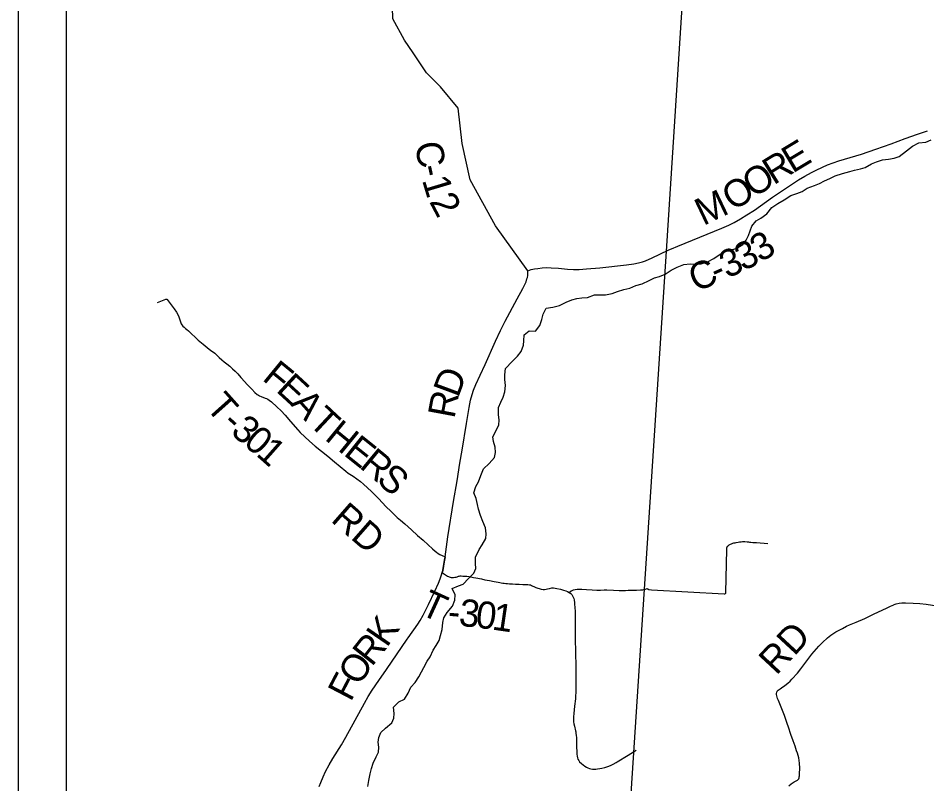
# Model space of a CAD drawing. Extents: x 0 to 34, y 0 to 22.
# Drawn here: x 1.876 to 3.772, y 15.584 to 17.181 of the extents above; entities that cross this region are included whole.
import ezdxf

# ---------------------------------------------------------------- set-up
doc = ezdxf.new("R2010")
doc.units = 0
for name, color, linetype in [('GM_X_County_Road', 7, 'Continuous'), ('GM_X_County_Road_Text', 7, 'Continuous'), ('GM_X_Major_River', 7, 'Continuous'), ('GM_X_Township_Road', 7, 'Continuous'), ('GM_X_Township_Road_Text', 7, 'Continuous'), ('GM_X_Township_Text', 7, 'Continuous'), ('SH_Data', 7, 'Continuous')]:
    doc.layers.add(name, color=color, linetype=linetype)

msp = doc.modelspace()

# ---------------------------------------------------------------- linework, layer by layer
at = {"layer": 'GM_X_County_Road'}
for points in [[(2.9395, 16.654), (2.8723, 16.7479), (2.8196, 16.8434), (2.8023, 16.9196), (2.7941, 16.9933), (2.7575, 17.0379), (2.7279, 17.0667), (2.7, 17.1083), (2.6825, 17.1348), (2.6581, 17.1799), (2.6533, 17.3472)], [(3.2393, 16.6998), (3.2526, 16.7055), (3.2987, 16.724), (3.3446, 16.743), (3.3587, 16.7494), (3.3698, 16.755), (3.3833, 16.7625), (3.3965, 16.7705), (3.4121, 16.7808), (3.4502, 16.8075), (3.5045, 16.8435), (3.5177, 16.8516), (3.5313, 16.8592), (3.5424, 16.8648), (3.565, 16.875), (3.5765, 16.8795), (3.5884, 16.8834), (3.6359, 16.8976), (3.6654, 16.9075), (3.6975, 16.9191), (3.7265, 16.9301), (3.7528, 16.9393), (3.7733, 16.9459)], [(2.9395, 16.654), (2.9467, 16.6564), (2.9533, 16.6579), (2.9601, 16.6591), (2.9694, 16.6603), (2.9788, 16.6608), (2.9882, 16.6605), (3.0037, 16.6592), (3.0222, 16.6574), (3.0346, 16.6568), (3.0469, 16.6569), (3.0623, 16.6578), (3.0901, 16.6602), (3.1457, 16.6663), (3.161, 16.6685), (3.1701, 16.6703), (3.179, 16.6727), (3.1848, 16.6748), (3.1989, 16.681), (3.2326, 16.6969), (3.2339, 16.6975), (3.2393, 16.6998)], [(2.767, 16.0576), (2.773, 16.0992), (2.7847, 16.1728), (2.7921, 16.2156), (2.7978, 16.2524), (2.8025, 16.28), (2.8113, 16.3352), (2.8169, 16.3689), (2.8201, 16.3841), (2.8233, 16.3962), (2.8263, 16.4051), (2.8309, 16.4166), (2.84, 16.4363), (2.8507, 16.4588), (2.8722, 16.507), (2.8828, 16.5295), (2.8925, 16.5489), (2.9171, 16.5956), (2.9292, 16.6172), (2.9333, 16.6255), (2.9358, 16.6311), (2.9378, 16.6369), (2.9386, 16.6401), (2.9395, 16.6444), (2.9398, 16.649), (2.9395, 16.654)], [(2.7607, 16.0249), (2.7619, 16.029), (2.7639, 16.038), (2.766, 16.0502), (2.767, 16.0576)], [(2.5044, 15.5781), (2.5075, 15.5869), (2.5123, 15.5984), (2.5176, 15.6096), (2.525, 15.6234), (2.5329, 15.6367), (2.551, 15.6653), (2.5602, 15.6813), (2.5987, 15.7522), (2.6065, 15.7657), (2.6148, 15.7789), (2.6288, 15.7994), (2.6448, 15.8223), (2.6875, 15.8856), (2.6896, 15.8886), (2.7098, 15.917), (2.7149, 15.9248), (2.7209, 15.9355), (2.732, 15.9577), (2.7453, 15.9858), (2.7529, 16.0027), (2.7564, 16.0113), (2.7594, 16.0201), (2.7607, 16.0249)]]:
    msp.add_lwpolyline(points, dxfattribs=at)
at = {"layer": 'GM_X_Major_River'}
for points in [[(3.7036, 16.8892), (3.7142, 16.8926), (3.7297, 16.904), (3.7421, 16.914), (3.7553, 16.9208), (3.7701, 16.9224), (3.7811, 16.9274)], [(2.841, 16.1436), (2.8368, 16.1569), (2.8345, 16.1667), (2.8318, 16.1788), (2.8272, 16.1909), (2.831, 16.2042), (2.8366, 16.2141), (2.8415, 16.227), (2.8471, 16.2407), (2.8592, 16.2521), (2.8697, 16.2643), (2.8724, 16.2749), (2.8716, 16.2863), (2.8681, 16.2976), (2.8662, 16.3078), (2.8737, 16.3211), (2.8793, 16.3329), (2.8797, 16.3424), (2.8781, 16.3545), (2.8785, 16.3689), (2.8833, 16.3803), (2.8882, 16.3902), (2.8916, 16.4016), (2.8931, 16.4148), (2.8919, 16.4273), (2.8919, 16.4368), (2.8933, 16.4501), (2.9069, 16.4645), (2.9178, 16.476), (2.9257, 16.4855), (2.9302, 16.4988), (2.9313, 16.5082), (2.9317, 16.5204), (2.9426, 16.5287), (2.9555, 16.528), (2.9649, 16.5398), (2.9687, 16.5524), (2.9716, 16.5634), (2.978, 16.5763), (2.992, 16.5782), (3.0053, 16.5817), (3.0192, 16.5886), (3.0313, 16.5932), (3.0415, 16.5963), (3.0521, 16.5975), (3.0639, 16.5986), (3.0786, 16.6036), (3.0885, 16.6037), (3.1017, 16.6041), (3.1153, 16.6068), (3.1267, 16.6107), (3.1399, 16.6153), (3.1524, 16.6176), (3.1648, 16.6233), (3.1784, 16.6268), (3.1924, 16.6337), (3.2038, 16.6394), (3.214, 16.6418), (3.2261, 16.6471), (3.2385, 16.6555), (3.251, 16.6613), (3.265, 16.667), (3.2782, 16.6682), (3.2888, 16.6679), (3.3013, 16.6683), (3.3145, 16.6729), (3.3274, 16.6794), (3.3406, 16.6886), (3.3512, 16.6947), (3.3614, 16.697), (3.3739, 16.7008), (3.3878, 16.7085), (3.395, 16.718), (3.3999, 16.7275), (3.4033, 16.7374), (3.407, 16.7468), (3.4157, 16.7579), (3.4255, 16.7636), (3.4379, 16.7728), (3.4485, 16.7857), (3.4613, 16.7945), (3.4742, 16.8021), (3.4882, 16.8113), (3.501, 16.8155), (3.5116, 16.8193), (3.5225, 16.8262), (3.5373, 16.8319), (3.5479, 16.8362), (3.5584, 16.8415), (3.5698, 16.8465), (3.5807, 16.8522), (3.5959, 16.8568), (3.611, 16.8611), (3.6212, 16.8638), (3.6333, 16.8669), (3.6435, 16.8692), (3.6563, 16.8768), (3.6669, 16.8814), (3.6794, 16.8853), (3.6923, 16.8868), (3.7036, 16.8892)], [(2.6061, 15.5783), (2.6079, 15.5908), (2.6105, 15.6045), (2.6135, 15.6158), (2.6169, 15.6268), (2.6229, 15.6401), (2.6278, 15.6496), (2.6285, 15.6606), (2.6273, 15.6708), (2.6288, 15.6803), (2.6326, 15.6906), (2.6424, 15.7001), (2.6556, 15.7108), (2.6601, 15.721), (2.6608, 15.7305), (2.6596, 15.7441), (2.6706, 15.7548), (2.6823, 15.7605), (2.6898, 15.7731), (2.6954, 15.7852), (2.7045, 15.7951), (2.712, 15.8069), (2.7177, 15.8172), (2.7225, 15.8267), (2.7293, 15.8396), (2.7361, 15.8491), (2.7421, 15.8624), (2.7481, 15.8726), (2.7549, 15.8829), (2.7571, 15.8935), (2.7605, 15.9057), (2.7623, 15.9201), (2.7646, 15.9299), (2.7713, 15.9413), (2.7823, 15.9543), (2.7875, 15.9672), (2.7879, 15.9778), (2.7814, 15.991), (2.7946, 15.9971), (2.8048, 16.0002), (2.8158, 16.012), (2.8267, 16.0231), (2.8312, 16.0333), (2.8304, 16.0435), (2.8307, 16.0568), (2.8382, 16.0724), (2.8443, 16.0823), (2.8522, 16.0956), (2.8525, 16.1054), (2.8513, 16.1175), (2.846, 16.1312), (2.841, 16.1436)]]:
    msp.add_lwpolyline(points, dxfattribs=at)
at = {"layer": 'GM_X_Township_Road'}
for points in [[(2.1668, 16.5877), (2.1846, 16.5946), (2.1854, 16.5948), (2.1862, 16.5947), (2.1869, 16.5944), (2.1872, 16.5939), (2.2017, 16.5745), (2.2064, 16.5679), (2.2095, 16.5631), (2.2117, 16.5578), (2.2135, 16.5517), (2.2155, 16.5454), (2.2166, 16.5431), (2.2178, 16.541), (2.2198, 16.5386), (2.2225, 16.5361), (2.2256, 16.5337), (2.2281, 16.5316), (2.2317, 16.5286), (2.252, 16.5095), (2.2619, 16.501), (2.2749, 16.4902), (2.2801, 16.4863), (2.2838, 16.4841), (2.2866, 16.482), (2.2896, 16.4795), (2.2917, 16.4775), (2.2958, 16.473), (2.301, 16.4681), (2.3061, 16.4644), (2.3116, 16.4602), (2.3176, 16.4552), (2.3234, 16.4498), (2.329, 16.4446), (2.3347, 16.439), (2.3411, 16.4316), (2.3418, 16.4308)], [(2.3418, 16.4308), (2.3546, 16.4161), (2.3636, 16.407), (2.3701, 16.4004), (2.3748, 16.3963), (2.3774, 16.3946), (2.3801, 16.393), (2.3829, 16.3917), (2.3917, 16.3886), (2.3945, 16.3875), (2.3973, 16.3861), (2.3999, 16.3844), (2.4047, 16.3806), (2.4162, 16.3702), (2.4251, 16.3617), (2.4331, 16.3531), (2.4445, 16.3394), (2.4596, 16.3221), (2.4648, 16.3167), (2.4842, 16.2986), (2.4961, 16.2881), (2.522, 16.2673), (2.5361, 16.2554), (2.5599, 16.2359), (2.5649, 16.2322), (2.5752, 16.2253), (2.583, 16.22), (2.5902, 16.2144), (2.5968, 16.2086), (2.6132, 16.1934), (2.6285, 16.1781), (2.6433, 16.1626), (2.6543, 16.1521), (2.6649, 16.1418), (2.6673, 16.1397)], [(2.6673, 16.1397), (2.6737, 16.1341), (2.6832, 16.1263), (2.6967, 16.1138), (2.7097, 16.1021), (2.7211, 16.0919), (2.7313, 16.0825), (2.7407, 16.0742), (2.746, 16.0695), (2.7492, 16.0668), (2.7523, 16.0644), (2.7559, 16.0623), (2.7611, 16.0599), (2.767, 16.0576)], [(3.0912, 15.9881), (3.0988, 15.9885), (3.1047, 15.9885), (3.1182, 15.9881), (3.1298, 15.9874), (3.1367, 15.9873), (3.1435, 15.9873), (3.1491, 15.9875), (3.1543, 15.9877), (3.1601, 15.9879), (3.1661, 15.9881), (3.1748, 15.9885), (3.1792, 15.9888), (3.1819, 15.9891), (3.1852, 15.99), (3.1882, 15.991), (3.1923, 15.9893), (3.1973, 15.9888), (3.3489, 15.9801), (3.3506, 15.9803), (3.3518, 15.9808), (3.3525, 15.9819), (3.3528, 15.9832), (3.3544, 16.0728), (3.3546, 16.0747), (3.355, 16.0763), (3.3562, 16.0793), (3.3574, 16.0805), (3.3586, 16.0815), (3.3597, 16.0823), (3.361, 16.0832), (3.3627, 16.084), (3.3646, 16.0848), (3.3669, 16.0856), (3.3692, 16.0863), (3.3718, 16.0868), (3.3743, 16.0873), (3.3783, 16.088), (3.3814, 16.0886), (3.3843, 16.0889), (3.3871, 16.0892), (3.3898, 16.0893), (3.3925, 16.0892), (3.3971, 16.0888), (3.4, 16.0885), (3.4023, 16.0882), (3.4051, 16.0879), (3.4088, 16.0875), (3.4163, 16.0871), (3.4406, 16.0855)], [(2.767, 16.0576), (2.766, 16.0502), (2.7639, 16.038), (2.7619, 16.029), (2.7607, 16.0249)], [(2.7607, 16.0249), (2.7638, 16.0226), (2.7698, 16.0183), (2.7719, 16.0171), (2.7738, 16.016), (2.7756, 16.0153), (2.7775, 16.0148), (2.7795, 16.0145), (2.782, 16.0144), (2.7846, 16.0145), (2.7872, 16.0148), (2.7901, 16.0152), (2.7918, 16.0157), (2.7948, 16.0169), (2.7965, 16.0172), (2.7983, 16.0174), (2.8007, 16.0174), (2.8041, 16.0173), (2.8079, 16.0171), (2.8126, 16.0167), (2.8173, 16.016), (2.8265, 16.0145), (2.8311, 16.0136), (2.8428, 16.0112), (2.8502, 16.0097), (2.8599, 16.0077), (2.8695, 16.0059), (2.8778, 16.0043), (2.8871, 16.0025), (2.8902, 16.0021), (2.8934, 16.0017), (2.8968, 16.0014), (2.9014, 16.0011), (2.9076, 16.0007), (2.9138, 16.0004), (2.9212, 16.0002), (2.929, 15.9997), (2.9327, 15.9995), (2.9363, 15.9994), (2.9396, 15.9993), (2.9427, 15.9991), (2.9452, 15.9986), (2.9475, 15.9976), (2.9499, 15.9963), (2.9523, 15.9954), (2.9565, 15.9935), (2.9677, 15.9897), (2.9715, 15.9894), (2.9746, 15.9895), (2.9776, 15.9897), (2.9807, 15.9905), (2.9849, 15.9916), (2.9894, 15.9926), (2.9929, 15.9928), (2.9968, 15.9923), (3.0004, 15.9916), (3.0074, 15.9896), (3.0139, 15.9875), (3.0188, 15.9861), (3.0222, 15.9851), (3.0258, 15.9832), (3.0299, 15.9863), (3.0323, 15.9874), (3.0347, 15.9882), (3.0386, 15.9891), (3.0428, 15.9897), (3.0436, 15.9897)], [(3.0258, 15.9832), (3.0294, 15.9807), (3.0312, 15.9787), (3.0329, 15.9761), (3.0342, 15.9733), (3.0352, 15.9704), (3.036, 15.9674), (3.037, 15.9613), (3.0377, 15.949), (3.038, 15.9459), (3.0385, 15.9213), (3.0383, 15.9034), (3.0384, 15.897), (3.0384, 15.8949)], [(3.0436, 15.9897), (3.0467, 15.99), (3.0524, 15.99), (3.0619, 15.9895), (3.0739, 15.9886), (3.0833, 15.9881), (3.0912, 15.9881)], [(3.4841, 15.5796), (3.4888, 15.5839), (3.4952, 15.5877), (3.5018, 15.5915), (3.5036, 15.593), (3.5047, 15.5946), (3.5054, 15.5965), (3.5059, 15.5985), (3.5061, 15.6008), (3.5064, 15.6049), (3.5067, 15.6165), (3.5065, 15.6272), (3.5049, 15.6382), (3.502, 15.6479), (3.5004, 15.6526), (3.4971, 15.6625), (3.4931, 15.6734), (3.4882, 15.6868), (3.4833, 15.702), (3.4808, 15.7095), (3.4751, 15.7264), (3.4628, 15.7577), (3.4606, 15.7617), (3.4595, 15.7645), (3.4587, 15.7675), (3.4583, 15.7705), (3.4584, 15.7725), (3.4591, 15.7751), (3.46, 15.777), (3.4616, 15.779), (3.4636, 15.7807), (3.466, 15.7823), (3.4688, 15.7842), (3.4714, 15.7859), (3.475, 15.7885), (3.4792, 15.7914), (3.4818, 15.7935), (3.4865, 15.7978), (3.4904, 15.8019), (3.5018, 15.8146), (3.509, 15.8237), (3.5318, 15.8544), (3.5467, 15.8709), (3.5543, 15.8788), (3.5648, 15.8882), (3.5719, 15.8941), (3.5824, 15.9007), (3.5957, 15.9082), (3.6047, 15.9126), (3.6109, 15.9156), (3.6243, 15.9209), (3.6429, 15.9288), (3.6622, 15.9385), (3.6876, 15.9505), (3.6959, 15.9543), (3.7029, 15.9574), (3.7038, 15.9577)], [(3.7038, 15.9577), (3.7082, 15.9593), (3.7139, 15.9605), (3.7201, 15.9611), (3.7274, 15.9612), (3.7435, 15.9607), (3.7573, 15.9597), (3.7709, 15.9585), (3.7839, 15.9562), (3.797, 15.9534), (3.8144, 15.9501), (3.8375, 15.9472), (3.8533, 15.9452), (3.8681, 15.9447), (3.8702, 15.9446), (3.8904, 15.9457), (3.908, 15.9462), (3.9223, 15.9465), (3.9345, 15.9454), (3.9407, 15.9449)], [(3.0384, 15.8949), (3.0384, 15.8879), (3.0387, 15.8572), (3.0394, 15.8294), (3.0397, 15.817), (3.0396, 15.7919), (3.0394, 15.777), (3.0392, 15.7643), (3.0391, 15.7612), (3.0371, 15.7457), (3.0362, 15.7384), (3.0353, 15.7306), (3.0348, 15.7239), (3.0347, 15.7206), (3.0348, 15.717), (3.0351, 15.7131), (3.0357, 15.7091), (3.0369, 15.7038), (3.0391, 15.6943), (3.0396, 15.692), (3.0399, 15.689), (3.0403, 15.6853), (3.0408, 15.68), (3.0413, 15.6736), (3.0412, 15.6687), (3.0413, 15.6598), (3.0416, 15.6518), (3.0419, 15.6459), (3.0424, 15.6417), (3.0431, 15.6379), (3.0442, 15.6351), (3.0457, 15.6325), (3.0476, 15.6299), (3.0512, 15.6263), (3.0548, 15.6234), (3.0588, 15.6206), (3.0619, 15.6187), (3.0649, 15.6172), (3.068, 15.616), (3.0709, 15.6152), (3.0744, 15.6147), (3.0781, 15.6146), (3.0814, 15.6147), (3.0851, 15.6151), (3.0895, 15.6157), (3.0942, 15.6166), (3.1002, 15.6182), (3.1067, 15.6202), (3.1119, 15.6224), (3.1179, 15.6251), (3.1236, 15.6282), (3.1261, 15.6297), (3.1489, 15.6433), (3.1657, 15.6541)]]:
    msp.add_lwpolyline(points, dxfattribs=at)
at = {"layer": 'GM_X_Township_Text'}
msp.add_lwpolyline([(8.7763, 18.7365), (7.7116, 18.8006), (7.6851, 18.802), (7.2653, 18.8305), (6.9608, 18.8511), (6.9477, 18.852), (6.9018, 18.8551), (6.7713, 18.864), (6.3469, 18.8928), (5.4766, 18.9518), (4.3125, 19.0308), (4.2973, 19.0318), (4.1694, 19.0405), (3.3833, 19.0938), (3.2714, 17.3671), (3.2279, 16.6952), (3.1822, 15.9898), (3.1607, 15.6594), (3.1102, 14.8789), (3.0682, 14.2309), (3.0665, 14.2054)], dxfattribs=at)
at = {"layer": 'SH_Data'}
for p, q in [((1.8763, 21.1054), (1.8763, 14.1054)), ((1.9763, 21.0054), (1.9763, 14.2054))]:
    msp.add_line(p, q, dxfattribs=at)

# ---------------------------------------------------------------- texts
at = {"layer": 'GM_X_County_Road_Text'}
for s, rotation, p in [('E', 31.0813, (3.4918, 16.8563)), ('C', 280.0982, (2.7036, 16.919)), ('R', 31.7596, (3.4523, 16.8319)), ('-', 282.3397, (2.7123, 16.8707)), ('O', 33.217, (3.4108, 16.8047)), ('1', 286.6415, (2.7185, 16.8434)), ('O', 32.3234, (3.3677, 16.7774)), ('2', 297.9166, (2.7331, 16.7985)), ('M', 25.5056, (3.3056, 16.7473)), ('3', 31.0928, (3.425, 16.6707)), ('3', 24.5549, (3.3555, 16.6374)), ('3', 26.2923, (3.389, 16.6527)), ('C', 23.6942, (3.2906, 16.6088)), ('-', 23.8897, (3.3335, 16.6276)), ('D', 69.6951, (2.7942, 16.3877)), ('R', 79.4257, (2.7863, 16.3442)), ('K', 55.574, (2.6455, 15.8666)), ('R', 51.6803, (2.6141, 15.8266)), ('O', 56.3221, (2.5871, 15.786)), ('F', 62.3725, (2.5701, 15.7534))]:
    msp.add_text(s, height=0.0568, rotation=rotation, dxfattribs=at).set_placement(p)
at = {"layer": 'GM_X_Township_Road_Text'}
for s, height, rotation, p in [('F', 0.0568, 320.6033, (2.3834, 16.4274)), ('E', 0.0568, 317.3463, (2.4123, 16.4036)), ('T', 0.0568, 311.7375, (2.2657, 16.3686)), ('A', 0.0568, 311.9772, (2.4426, 16.3758)), ('T', 0.0568, 316.9085, (2.4798, 16.3348)), ('-', 0.0568, 317.9692, (2.2988, 16.3321)), ('3', 0.0568, 319.5045, (2.3174, 16.3154)), ('H', 0.0568, 320.703, (2.5139, 16.3031)), ('0', 0.0568, 319.598, (2.344, 16.2926)), ('E', 0.0568, 321.2837, (2.5531, 16.271)), ('1', 0.0568, 318.5164, (2.3705, 16.2701)), ('R', 0.0568, 320.3563, (2.5861, 16.2446)), ('S', 0.0568, 317.8637, (2.6215, 16.2153)), ('RD', 0.05682, 318.8291, (2.5266, 16.1325)), ('T', 0.0568, 335.4784, (2.7121, 15.9388)), ('3', 0.0568, 353.7851, (2.7941, 15.9139)), ('0', 0.0568, 353.0351, (2.8287, 15.9101)), ('1', 0.0568, 351.6911, (2.8631, 15.9059)), ('-', 0.0568, 355.1736, (2.7712, 15.9158)), ('RD', 0.05682, 47.0941, (3.4579, 15.8086))]:
    msp.add_text(s, height=height, rotation=rotation, dxfattribs=at).set_placement(p)

doc.saveas('drawing.dxf')
